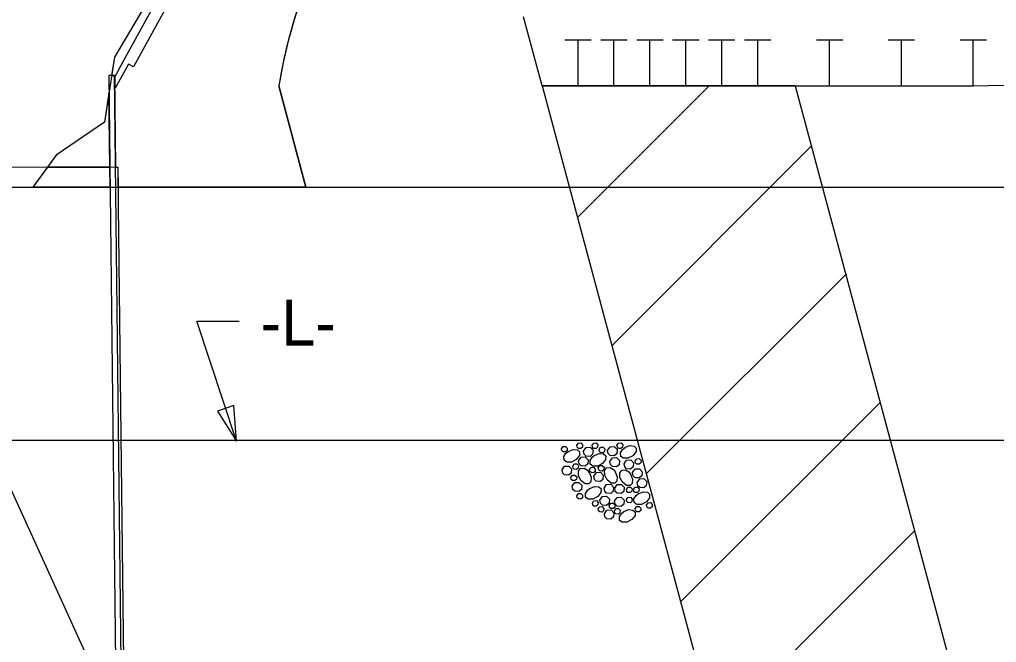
# Model space of a CAD drawing. Extents: x -20 to 509, y -659 to 21.
# Drawn here: x 153.38 to 195.85, y -378.86 to -351.75 of the extents above; entities that cross this region are included whole.
import ezdxf

# ---------------------------------------------------------------- set-up
doc = ezdxf.new("R2010")
doc.units = 0
for name, color, linetype in [('Arrowhead Terminators CELL', 7, 'Continuous'), ('Default', 7, 'Continuous'), ('Dimension Lines', 7, 'Continuous'), ('Exist Hydro Stream or Body of Water', 7, 'Continuous'), ('Exist Structure Major Deck Tunnel Box Culvert', 7, 'Continuous'), ('Mis Object Lines', 7, 'Continuous'), ('Miscellaneous Lines CELL', 7, 'Continuous'), ('Prop EOT', 7, 'Continuous'), ('Prop Horizontal Alignment', 7, 'Continuous'), ('Sup Concrete Girder Lines', 7, 'Continuous'), ('Text', 7, 'Continuous')]:
    doc.layers.add(name, color=color, linetype=linetype)

msp = doc.modelspace()

# ---------------------------------------------------------------- linework, layer by layer
at = {"layer": 'Arrowhead Terminators CELL'}
msp.add_lwpolyline([(162.807, -370.099), (162.694, -368.557), (161.982, -368.792)], close=True, dxfattribs=at)
at = {"layer": 'Default'}
for p, q in [((177.088, -352.635), (178.233, -352.635)), ((177.661, -354.635), (177.661, -352.635)), ((178.65, -352.635), (179.796, -352.635)), ((179.223, -354.635), (179.223, -352.635)), ((180.213, -352.635), (181.358, -352.635)), ((180.786, -354.635), (180.786, -352.635)), ((181.775, -352.635), (182.921, -352.635)), ((182.348, -354.635), (182.348, -352.635)), ((183.338, -352.635), (184.483, -352.635)), ((183.911, -354.635), (183.911, -352.635)), ((184.9, -352.635), (186.046, -352.635)), ((185.473, -354.635), (185.473, -352.635)), ((188.025, -352.635), (189.171, -352.635)), ((188.598, -354.635), (188.598, -352.635)), ((191.15, -352.635), (192.296, -352.635)), ((191.723, -354.635), (191.723, -352.635)), ((194.275, -352.635), (195.421, -352.635)), ((194.848, -354.635), (194.848, -352.635)), ((194.848, -354.635), (237.897, -353.774)), ((165.83, -359.052), (164.646, -354.635)), ((176.098, -354.635), (194.848, -354.635)), ((157.266, -354.939), (157.07, -356.225)), ((157.303, -358.186), (157.266, -354.939)), ((154.587, -358.18), (153.951, -359.052)), ((154.587, -358.18), (157.303, -358.186)), ((157.303, -358.186), (154.587, -358.18)), ((157.313, -359.052), (157.303, -358.186)), ((157.313, -359.052), (153.951, -359.052)), ((153.951, -359.052), (157.313, -359.052)), ((157.663, -359.052), (165.83, -359.052)), ((165.83, -359.052), (157.663, -359.052))]:
    msp.add_line(p, q, dxfattribs=at)
for points in [[(162.2, -345.445), (157.501, -353.399), (157.07, -356.225), (154.971, -357.654), (153.951, -359.052)], [(162.2, -345.445), (157.501, -353.399), (157.381, -354.185)], [(157.381, -354.185), (157.508, -354.184), (157.553, -358.186)], [(157.07, -356.225), (154.971, -357.654), (154.587, -358.18)], [(157.553, -358.186), (157.653, -358.186), (157.663, -359.052)]]:
    msp.add_lwpolyline(points, dxfattribs=at)
msp.add_arc((186.949, -358.362), 22.612, 123.2178, 170.5127, dxfattribs=at)
at = {"layer": 'Dimension Lines'}
for p, q in [((162.807, -370.099), (161.089, -364.881)), ((161.089, -364.881), (162.926, -364.881))]:
    msp.add_line(p, q, dxfattribs=at)
at = {"layer": 'Exist Hydro Stream or Body of Water'}
msp.add_lwpolyline([(172.62, -414.952), (171.034, -412.028), (162.209, -394.718), (158.096, -386.345), (157.248, -386.282), (157.152, -381.329), (150.426, -366.566), (150.897, -357.105), (151.634, -355.242)], dxfattribs=at)
at = {"layer": 'Exist Structure Major Deck Tunnel Box Culvert'}
for points in [[(157.532, -354.229), (157.889, -353.578), (162.458, -345.249), (163.256, -343.793), (163.476, -343.914), (162.677, -345.369), (162.896, -345.489), (158.328, -353.819), (158.108, -353.698), (157.538, -354.739), (157.532, -354.229)], [(157.508, -354.184), (157.258, -354.186), (157.619, -386.105), (157.869, -386.102), (157.508, -354.184)], [(105.001, -374.19), (104.949, -369.454), (104.839, -359.537), (104.823, -358.08), (122.822, -358.116), (139.71, -358.15), (157.653, -358.186), (157.672, -359.848), (157.785, -369.851), (157.896, -379.673), (157.921, -381.85), (139.968, -381.814), (123.014, -381.779), (105.085, -381.743)]]:
    msp.add_lwpolyline(points, dxfattribs=at)
at = {"layer": 'Mis Object Lines'}
for p, q in [((176.098, -354.635), (184.36, -385.469)), ((187.098, -354.635), (176.098, -354.635)), ((177.635, -360.37), (183.369, -354.635)), ((187.098, -354.635), (195.36, -385.469)), ((179.129, -365.947), (187.804, -357.271)), ((180.623, -371.523), (189.299, -362.848)), ((182.118, -377.1), (190.793, -368.425)), ((183.612, -382.677), (192.287, -374.001))]:
    msp.add_line(p, q, dxfattribs=at)
at = {"layer": 'Miscellaneous Lines CELL'}
for points in [[(176.943, -370.429), (177.01, -370.334), (177.117, -370.327), (177.192, -370.405), (177.181, -370.513), (177.115, -370.568), (177.009, -370.561), (176.959, -370.512), (176.943, -370.429)], [(177.611, -370.283), (177.679, -370.187), (177.786, -370.181), (177.861, -370.258), (177.85, -370.367), (177.783, -370.422), (177.677, -370.414), (177.628, -370.366), (177.611, -370.283)], [(177.897, -370.532), (178.009, -370.372), (178.188, -370.362), (178.312, -370.491), (178.294, -370.672), (178.183, -370.764), (178.007, -370.751), (177.924, -370.67), (177.897, -370.532)], [(178.274, -370.283), (178.342, -370.187), (178.449, -370.181), (178.524, -370.258), (178.513, -370.367), (178.446, -370.422), (178.34, -370.414), (178.291, -370.366), (178.274, -370.283)], [(178.577, -370.466), (178.644, -370.37), (178.751, -370.364), (178.826, -370.442), (178.815, -370.55), (178.749, -370.605), (178.643, -370.598), (178.593, -370.549), (178.577, -370.466)], [(178.944, -370.507), (179.056, -370.348), (179.235, -370.338), (179.359, -370.467), (179.341, -370.647), (179.231, -370.739), (179.054, -370.727), (178.971, -370.646), (178.944, -370.507)], [(179.354, -370.283), (179.421, -370.187), (179.529, -370.181), (179.603, -370.258), (179.593, -370.367), (179.526, -370.422), (179.42, -370.414), (179.37, -370.366), (179.354, -370.283)], [(179.696, -370.38), (179.905, -370.297), (180.098, -370.313), (180.189, -370.4), (180.186, -370.557), (180.047, -370.734), (179.833, -370.842), (179.631, -370.845), (179.517, -370.764), (179.506, -370.603), (179.598, -370.459), (179.704, -370.375)], [(177.233, -370.552), (177.442, -370.469), (177.635, -370.486), (177.727, -370.573), (177.724, -370.729), (177.585, -370.906), (177.37, -371.014), (177.168, -371.017), (177.054, -370.936), (177.043, -370.775), (177.136, -370.631), (177.241, -370.547)], [(177.686, -370.953), (177.798, -370.794), (177.977, -370.784), (178.101, -370.913), (178.083, -371.093), (177.973, -371.185), (177.796, -371.172), (177.713, -371.092), (177.686, -370.953)], [(178.372, -370.721), (178.581, -370.638), (178.774, -370.655), (178.865, -370.742), (178.862, -370.898), (178.723, -371.076), (178.509, -371.183), (178.307, -371.187), (178.193, -371.106), (178.182, -370.945), (178.274, -370.8), (178.38, -370.716)], [(179.049, -370.985), (179.161, -370.825), (179.34, -370.815), (179.464, -370.944), (179.446, -371.125), (179.336, -371.216), (179.159, -371.204), (179.076, -371.123), (179.049, -370.985)], [(176.967, -371.353), (177.079, -371.194), (177.258, -371.184), (177.383, -371.313), (177.365, -371.493), (177.254, -371.585), (177.077, -371.572), (176.994, -371.492), (176.967, -371.353)], [(177.429, -371.189), (177.496, -371.093), (177.604, -371.087), (177.678, -371.164), (177.667, -371.273), (177.601, -371.328), (177.495, -371.32), (177.445, -371.272), (177.429, -371.189)], [(178.163, -371.339), (178.23, -371.243), (178.337, -371.237), (178.412, -371.315), (178.401, -371.423), (178.335, -371.478), (178.229, -371.47), (178.179, -371.422), (178.163, -371.339)], [(178.541, -371.263), (178.609, -371.167), (178.716, -371.161), (178.791, -371.239), (178.78, -371.347), (178.714, -371.402), (178.607, -371.395), (178.558, -371.346), (178.541, -371.263)], [(179.282, -371.439), (179.365, -371.648), (179.349, -371.841), (179.262, -371.932), (179.106, -371.929), (178.928, -371.79), (178.821, -371.576), (178.817, -371.373), (178.898, -371.26), (179.059, -371.249), (179.203, -371.341), (179.288, -371.447)], [(179.662, -371.082), (179.774, -370.923), (179.953, -370.913), (180.077, -371.041), (180.059, -371.222), (179.949, -371.314), (179.772, -371.301), (179.689, -371.221), (179.662, -371.082)], [(180.15, -370.965), (180.217, -370.869), (180.324, -370.863), (180.399, -370.941), (180.388, -371.049), (180.322, -371.104), (180.216, -371.097), (180.166, -371.048), (180.15, -370.965)], [(177.352, -371.68), (177.42, -371.584), (177.527, -371.578), (177.602, -371.655), (177.591, -371.764), (177.524, -371.819), (177.418, -371.811), (177.369, -371.763), (177.352, -371.68)], [(178.144, -371.466), (178.227, -371.675), (178.21, -371.868), (178.123, -371.959), (177.967, -371.956), (177.789, -371.818), (177.682, -371.603), (177.678, -371.401), (177.759, -371.287), (177.92, -371.276), (178.065, -371.368), (178.149, -371.474)], [(178.345, -371.624), (178.457, -371.465), (178.636, -371.455), (178.76, -371.584), (178.742, -371.764), (178.632, -371.856), (178.455, -371.843), (178.372, -371.763), (178.345, -371.624)], [(179.947, -371.54), (180.03, -371.75), (180.013, -371.942), (179.926, -372.034), (179.77, -372.031), (179.592, -371.892), (179.485, -371.677), (179.481, -371.475), (179.562, -371.361), (179.723, -371.351), (179.868, -371.443), (179.952, -371.549)], [(180.035, -371.471), (180.147, -371.312), (180.326, -371.302), (180.45, -371.431), (180.432, -371.611), (180.322, -371.703), (180.145, -371.691), (180.062, -371.61), (180.035, -371.471)], [(177.409, -372.065), (177.521, -371.905), (177.7, -371.895), (177.825, -372.024), (177.807, -372.205), (177.696, -372.297), (177.52, -372.284), (177.436, -372.203), (177.41, -372.065)], [(178.168, -372.158), (178.378, -372.075), (178.57, -372.092), (178.662, -372.179), (178.659, -372.335), (178.52, -372.513), (178.305, -372.62), (178.103, -372.624), (177.989, -372.543), (177.979, -372.382), (178.071, -372.237), (178.177, -372.153)], [(178.793, -372.144), (178.905, -371.984), (179.084, -371.974), (179.209, -372.103), (179.191, -372.284), (179.08, -372.376), (178.903, -372.363), (178.82, -372.282), (178.793, -372.144)], [(179.254, -372.151), (179.366, -371.991), (179.545, -371.981), (179.669, -372.11), (179.651, -372.291), (179.541, -372.383), (179.364, -372.37), (179.281, -372.289), (179.254, -372.151)], [(179.764, -372.2), (179.831, -372.104), (179.939, -372.098), (180.013, -372.175), (180.002, -372.284), (179.936, -372.339), (179.83, -372.331), (179.78, -372.283), (179.764, -372.2)], [(180.068, -372.2), (180.135, -372.104), (180.242, -372.098), (180.317, -372.175), (180.306, -372.284), (180.24, -372.339), (180.134, -372.331), (180.084, -372.283), (180.068, -372.2)], [(180.231, -371.901), (180.343, -371.742), (180.522, -371.732), (180.646, -371.86), (180.628, -372.041), (180.518, -372.133), (180.341, -372.12), (180.258, -372.04), (180.231, -371.901)], [(177.611, -372.482), (177.679, -372.386), (177.786, -372.38), (177.861, -372.457), (177.85, -372.566), (177.783, -372.621), (177.677, -372.613), (177.628, -372.565), (177.611, -372.482)], [(178.612, -372.666), (178.724, -372.507), (178.903, -372.497), (179.027, -372.626), (179.009, -372.806), (178.899, -372.898), (178.722, -372.886), (178.639, -372.805), (178.612, -372.666)], [(180.28, -372.391), (180.49, -372.308), (180.683, -372.325), (180.774, -372.412), (180.771, -372.568), (180.632, -372.746), (180.418, -372.853), (180.215, -372.857), (180.101, -372.776), (180.091, -372.614), (180.183, -372.47), (180.289, -372.386)], [(178.284, -372.793), (178.351, -372.697), (178.458, -372.691), (178.533, -372.769), (178.522, -372.877), (178.456, -372.932), (178.35, -372.924), (178.3, -372.876), (178.284, -372.793)], [(179.016, -372.9), (179.083, -372.804), (179.19, -372.798), (179.265, -372.875), (179.254, -372.984), (179.188, -373.039), (179.082, -373.031), (179.032, -372.983), (179.016, -372.9)], [(179.251, -372.706), (179.363, -372.547), (179.542, -372.537), (179.666, -372.666), (179.648, -372.846), (179.538, -372.938), (179.361, -372.926), (179.278, -372.845), (179.251, -372.706)], [(179.764, -372.646), (179.831, -372.551), (179.939, -372.545), (180.013, -372.622), (180.002, -372.73), (179.936, -372.786), (179.83, -372.778), (179.78, -372.73), (179.764, -372.646)], [(180.147, -373.039), (180.215, -372.944), (180.322, -372.938), (180.397, -373.015), (180.386, -373.123), (180.319, -373.179), (180.213, -373.171), (180.164, -373.123), (180.147, -373.039)], [(180.64, -372.88), (180.707, -372.784), (180.814, -372.778), (180.889, -372.855), (180.878, -372.964), (180.812, -373.019), (180.706, -373.011), (180.656, -372.963), (180.64, -372.88)], [(178.536, -373.053), (178.604, -372.957), (178.711, -372.951), (178.786, -373.028), (178.775, -373.137), (178.709, -373.192), (178.603, -373.184), (178.553, -373.136), (178.537, -373.053)], [(178.805, -373.259), (178.917, -373.1), (179.096, -373.09), (179.22, -373.219), (179.202, -373.399), (179.092, -373.491), (178.915, -373.478), (178.832, -373.398), (178.805, -373.259)], [(179.242, -373.133), (179.309, -373.037), (179.417, -373.031), (179.491, -373.108), (179.48, -373.217), (179.414, -373.272), (179.308, -373.264), (179.258, -373.216), (179.242, -373.133)], [(179.648, -373.164), (179.858, -373.081), (180.05, -373.098), (180.142, -373.185), (180.139, -373.341), (180, -373.518), (179.785, -373.626), (179.583, -373.629), (179.469, -373.548), (179.458, -373.387), (179.551, -373.243), (179.657, -373.159)]]:
    msp.add_lwpolyline(points, dxfattribs=at)
at = {"layer": 'Prop EOT'}
msp.add_line((-3.076, -359.052), (237.897, -359.052), dxfattribs=at)
at = {"layer": 'Prop Horizontal Alignment'}
msp.add_line((70.294, -370.052), (237.897, -370.052), dxfattribs=at)
msp.add_line((70.294, -370.052), (237.897, -370.052), dxfattribs=at)
at = {"layer": 'Sup Concrete Girder Lines'}
for p, q in [((176.098, -354.635), (175.294, -351.635)), ((164.646, -354.635), (165.83, -359.052)), ((164.646, -354.635), (165.83, -359.052))]:
    msp.add_line(p, q, dxfattribs=at)
msp.add_arc((186.949, -358.362), 22.612, 90.1461, 170.5127, dxfattribs=at)

# ---------------------------------------------------------------- texts
at = {"layer": 'Text'}
msp.add_text('-L-', height=2, dxfattribs=at).set_placement((163.862, -365.94))

doc.saveas('drawing.dxf')
